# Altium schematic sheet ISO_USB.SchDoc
size A3; SheetNumber: 4; SheetTotal: 4
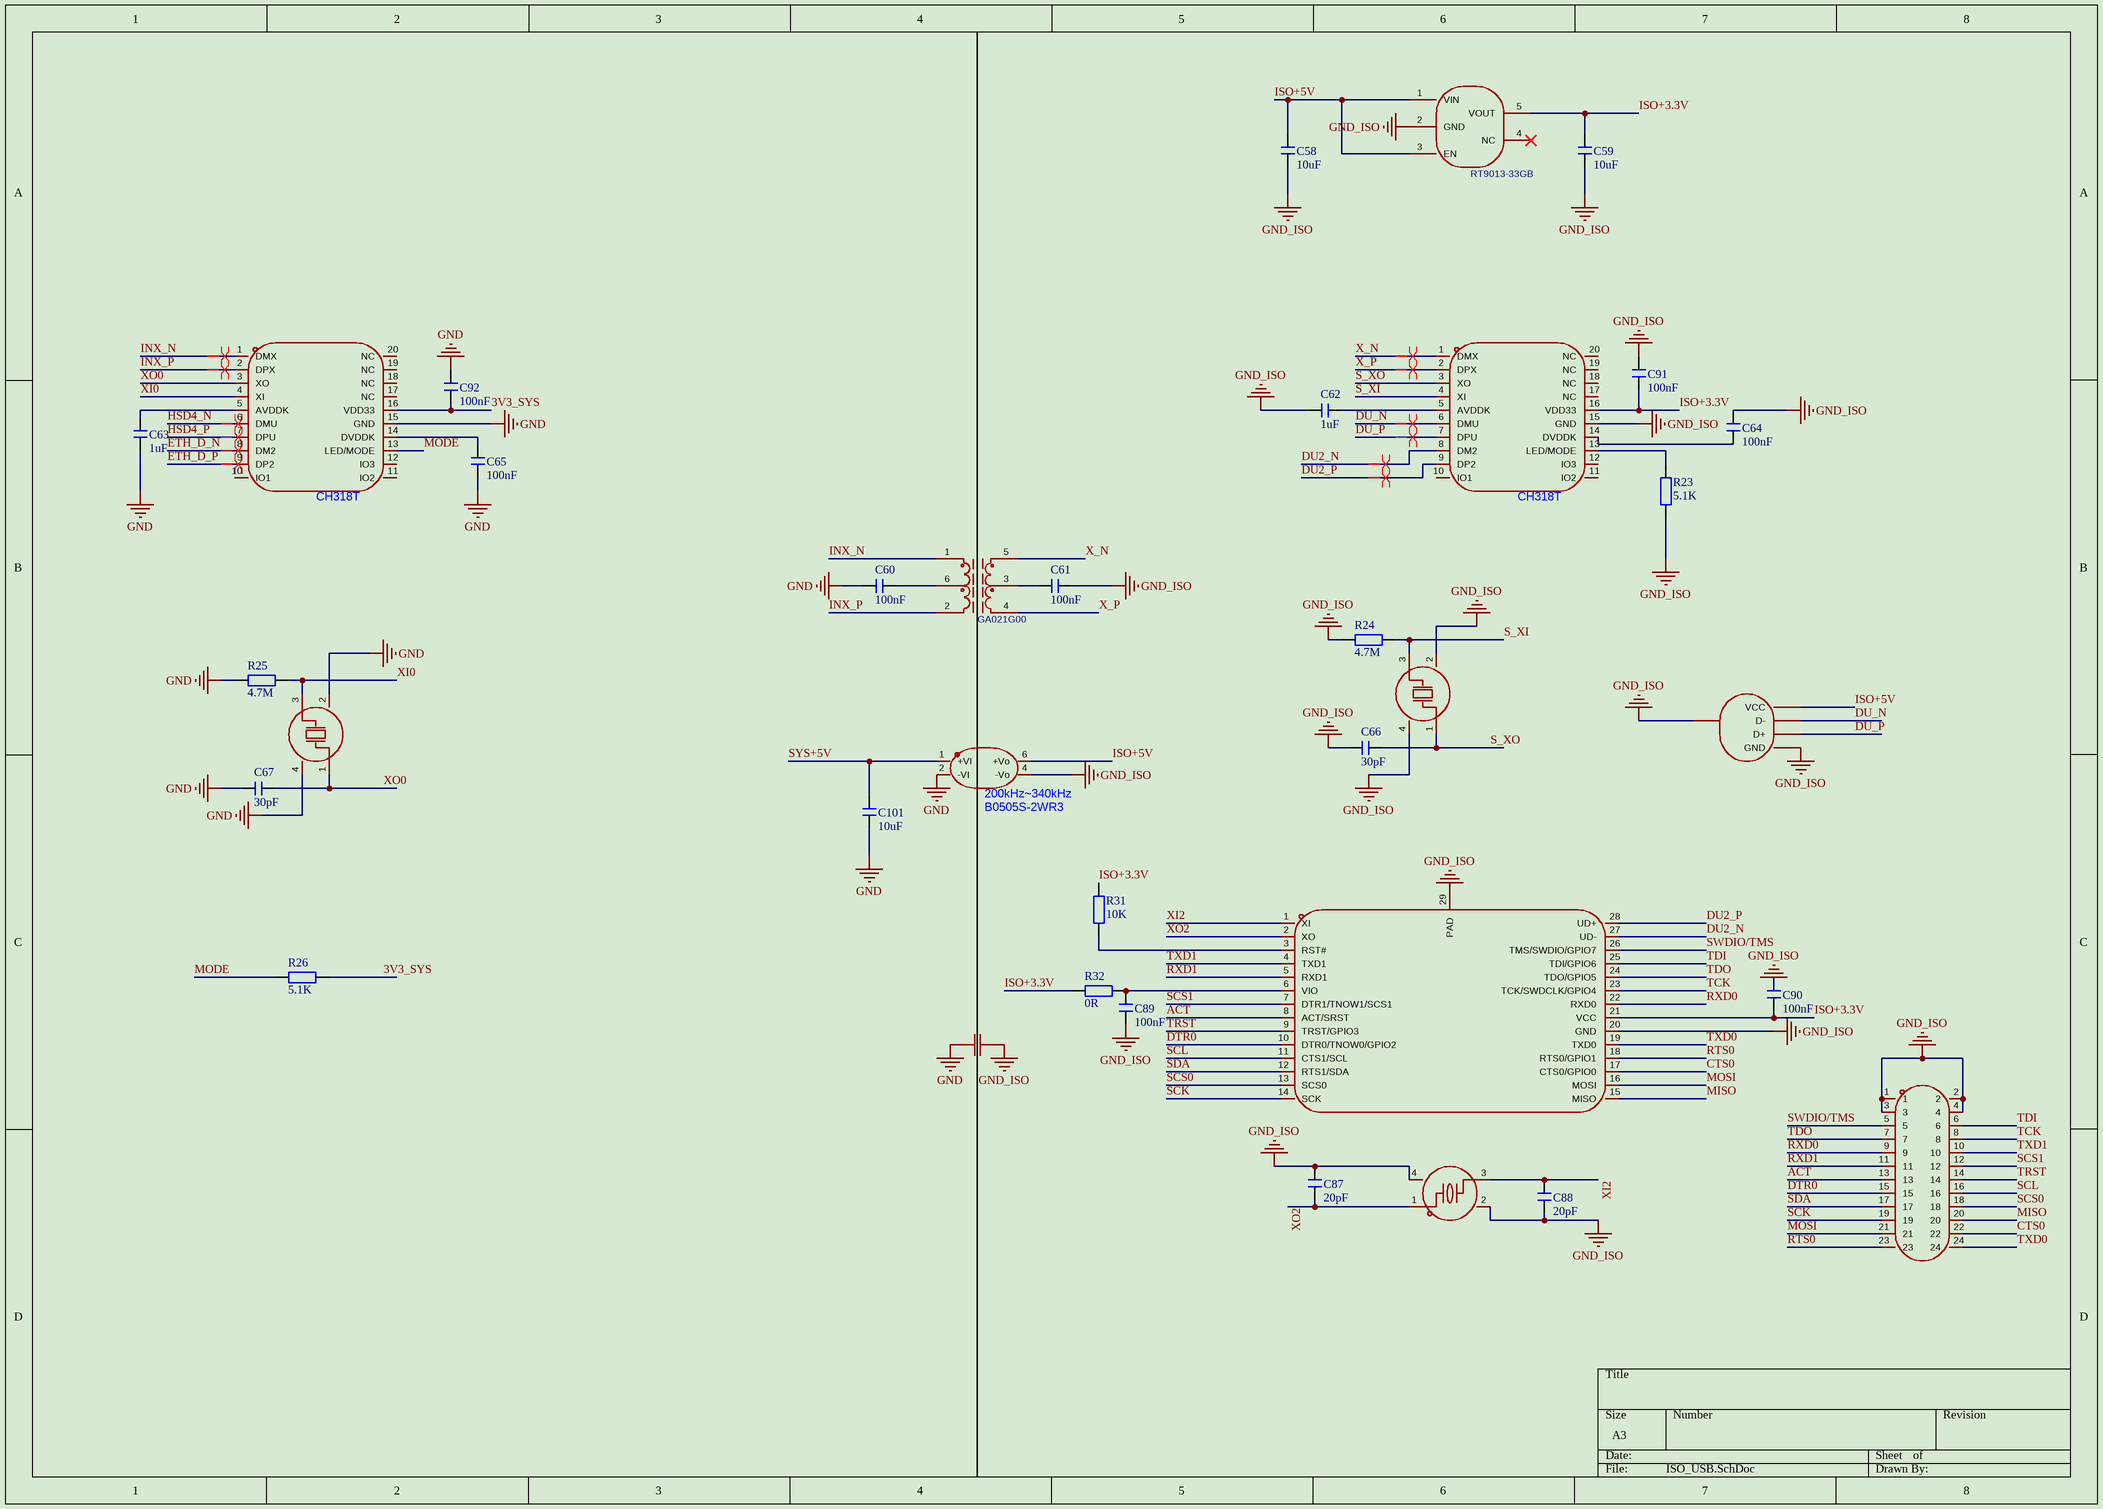
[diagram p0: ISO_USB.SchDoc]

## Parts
C58  10uF  [C 0805_L]
C59  10uF  [C 0805_L]
C60  100nF  [C 0603_L]
C61  100nF  [C 0603_L]
C62  1uF  [C 0603_L]
C63  1uF  [C 0603_L]
C64  100nF  [C 0603_L]
C65  100nF  [C 0603_L]
C66  30pF  [C 0603_L]
C67  30pF  [C 0603_L]
C86  q222m060110fq55250l7579  [CAP-TH_L8.0-W4.5-P7.50-D0.6]  (value not drawn)
C87  20pF  [C 0603_L]
C88  20pF  [C 0603_L]
C89  100nF  [C 0402_L]
C90  100nF  [C 0402_L]
C91  100nF  [C 0603_L]
C92  100nF  [C 0603_L]
C101  10uF  [C 0805_L]
H1  x6521wr-2x12h-c60d30  [HDR-TH_24P-P2.54-H-M-R2-C12-S2.54]  (value not drawn)
R23  5.1K  [R 0603_L]
R24  4.7M  [R 0603_L]
R25  4.7M  [R 0603_L]
R26  5.1K  [R 0603_L]
R31  10K  [R 0402_L]
R32  0R  [R 0402_L]
U8  rt9013-33gb  [SOT-23-5_L3.0-W1.7-P0.95-LS2.8-BL]
U9  ga021g00  [FILTER-SMD_6P-L4.5-W3.4_GA021G00]
U10  LCSC Part Name: CH318T  [TSSOP-20_L6.5-W4.4-P0.65-LS6.4-BL]  (hidden comment: ch318t_c42387966)
U11  LCSC Part Name: CH318T  [TSSOP-20_L6.5-W4.4-P0.65-LS6.4-BL]  (hidden comment: ch318t_c42387966)
U12  value 200kHz~340kHz  ManufacturerPart: B0505S-2WR3  [PWRM-TH_BXXXXS-2WR3]  (hidden comment: b0505s-2wr3_c7465195)
U15  ch347f  [QFN-28_L4.0-W4.0-P0.40-BL-EP2.7]  (value not drawn)
USB5  af 90° wjdg  [USB-A-TH_AF-WJDG]  (value not drawn)
X3  x322520msb4si  [CRYSTAL-SMD_4P-L3.2-W2.5-BL-2]  (value not drawn)
X4  x322520msb4si  [CRYSTAL-SMD_4P-L3.2-W2.5-BL-2]  (value not drawn)
X5  xl2el89coi-111ylc-8m  [CRYSTAL-SMD_4P-L3.2-W2.5-BL-1]  (value not drawn)

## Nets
GND: C60.2 C63.1 C65.1 C67.2 C86.1 C92.1 C101.1 R25.2 U10.15(GND) U12.2(-VI) X4.2(GND) X4.4(GND)
GND_ISO: C58.1 C59.1 C61.1 C62.2 C64.1 C66.2 C86.2 C87.1 C88.2 C89.2 C90.1 C91.1 H1.1 H1.2 H1.3 H1.4 R23.2 R24.2 U8.2(GND) U11.15(GND) U12.4(-Vo) U15.20(GND) U15.29(PAD) USB5.4(GND) USB5.5(SHLD) X3.2(GND) X3.4(GND) X5.2(GND) X5.4(GND)
3V3_SYS: C92.2 R26.1 U10.16(VDD33)
ACT: H1.13 U15.8(ACT/SRST)
CTS0: H1.22 U15.17(CTS0/GPIO0)
DTR0: H1.15 U15.10(DTR0/TNOW0/GPIO2)
DU2_N: U11.8(DM2) U15.27(UD-)
DU2_P: U11.9(DP2) U15.28(UD+)
DU_N: U11.6(DMU) USB5.2(D-)
DU_P: U11.7(DPU) USB5.3(D+)
ETH_D_N: U10.8(DM2)
ETH_D_P: U10.9(DP2)
HSD4_N: U10.6(DMU)
HSD4_P: U10.7(DPU)
INX_N: U9.1 U10.1(DMX)
INX_P: U9.2 U10.2(DPX)
ISO+3.3V: C59.2 C90.2 C91.2 R31.1 R32.1 U8.5(VOUT) U11.16(VDD33) U15.21(VCC)
ISO+5V: C58.2 U8.1(VIN) U8.3(EN) U12.6(+Vo) USB5.1(VCC)
MISO: H1.20 U15.15(MISO)
MODE: R26.2 U10.13(LED/MODE)
MOSI: H1.21 U15.16(MOSI)
RTS0: H1.23 U15.18(RTS0/GPIO1)
RXD0: H1.9 U15.22(RXD0)
RXD1: H1.11 U15.5(RXD1)
S_XI: R24.1 U11.4(XI) X3.3(OSC2)
S_XO: C66.1 U11.3(XO) X3.1(OSC1)
SCK: H1.19 U15.14(SCK)
SCL: H1.16 U15.11(CTS1/SCL)
SCS0: H1.18 U15.13(SCS0)
SCS1: H1.12 U15.7(DTR1/TNOW1/SCS1)
SDA: H1.17 U15.12(RTS1/SDA)
SWDIO/TMS: H1.5 U15.26(TMS/SWDIO/GPIO7)
SYS+5V: C101.2 U12.1(+VI)
TCK: H1.8 U15.23(TCK/SWDCLK/GPIO4)
TDI: H1.6 U15.25(TDI/GPIO6)
TDO: H1.7 U15.24(TDO/GPIO5)
TRST: H1.14 U15.9(TRST/GPIO3)
TXD0: H1.24 U15.19(TXD0)
TXD1: H1.10 U15.4(TXD1)
X_N: U9.5 U11.1(DMX)
X_P: U9.4 U11.2(DPX)
XI0: R25.1 U10.4(XI) X4.3(OSC2)
XI2: C88.1 U15.1(XI) X5.3
XO0: C67.1 U10.3(XO) X4.1(OSC1)
XO2: C87.2 U15.2(XO) X5.1
NetC60_1: C60.1 U9.6
NetC61_2: C61.2 U9.3
NetC62_1: C62.1 U11.5(AVDDK)
NetC63_2: C63.2 U10.5(AVDDK)
NetC64_2: C64.2 U11.14(DVDDK)
NetC65_2: C65.2 U10.14(DVDDK)
NetC89_1: C89.1 R32.2 U15.6(VIO)
NetR23_1: R23.1 U11.13(LED/MODE)
NetR31_2: R31.2 U15.3(RST#)

Not connected (* = marked no-connect by the designer): U8 4(NC)*; U10 10(IO1) 11(IO2) 12(IO3) 17(NC) 18(NC) 19(NC) 20(NC); U11 10(IO1) 11(IO2) 12(IO3) 17(NC) 18(NC) 19(NC) 20(NC)

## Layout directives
differential pair; differential pair class 90ohm: DU2_N, DU2_P, DU_N, DU_P, ETH_D_N, ETH_D_P, HSD4_N, HSD4_P
differential pair; differential pair class 100ohm: INX_N, INX_P, X_N, X_P

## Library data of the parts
C58-C67 C87-C92 C101 = C: 无极性贴片电容; 版权归属: 源创客; 材质: X7R
C86 = q222m060110fq55250l7579: 容值:2.2nF;精度:±20%;工作电压(AC):300V;防护等级:Y2;; Manufacturer: QNR(勤宏科技); AddInBom: yes; ModelId: 6309ea5c534b4b05939c21f9c59ffb79; ModelTransform: 354.33,177.165,0,0,0,0,0,0,-196.85; Value: 2.2nF; Tolerance: ±20%; Voltage(AC): 300V; Ratings: Y2
H1 = x6521wr-2x12h-c60d30: 插针结构:2x12P;间距:2.54mm;行距:2.54mm;圆针/方针:方针;排数:双排;总PIN位数:24P;额定电流:3A;额定电压:250V;配合针长度:-;塑高:2.5mm;端接针长度:-;触头材质:黄铜;触头镀层:金;工作温度:-40℃~+105℃;颜色:黑色;; Manufacturer: XKB Connection(中国星坤); Symbol: X6521WR-2×12H-C30D60; AddInBom: yes; ModelId: c87603f207fc4d939d696e0588895b6d; ModelName: HDR-TH_24P-P2.54-M-WI-2X12P; ModelTransform: 1199.9976,507.873,0,0,0,0,0,-190.945,-118.11; Pin Structure: 2x12P; Pitch: 2.54mm; Circluar Pins/Square Pins: 方针; Current Rating: 3A; Voltage Rating (Max): 250V
R23-R26 R31 R32 = R: 贴片电阻; 版权归属: 源创客
U8 = rt9013-33gb: 输出极性:正极;工作电压:5.5V;输出电压:3.3V;输出电流:500mA;电源纹波抑制比(PSRR):50dB@(10kHz);输出类型:固定;; Manufacturer: RICHTEK(立锜); AddInBom: yes; ModelId: 0a2a1b8f50944f73965918ad6e5fe167; ModelName: SOT-23-5_L2.9-W1.6-H1.1-LS2.8-P0.95; ModelTransform: 118.60433,114.173,0,90,0,0,0.0005,0.0005,0; Output Configuration: 正极; Voltage - Supply: 5.5V; Output Voltage: 3.3V; Output Current: 500mA; Voltage Dropout: 400mV@(500mA); standby current: 25uA; Noise: 30uVrms; Output Type: 固定; Number of Outputs: 1
U9 = ga021g00: 线路数:4;电感@频率:120uH@100kHz;阻抗@频率:-;直流电阻(DCR):1.2Ω;; Manufacturer: CND-tek(磁联达); AddInBom: yes; ModelId: 47185f9e5e204908b0c4690c3dbe201c; ModelTransform: 181.18074,133.858,0,0,0,0,0.001,-0.001,0; Number of Lines: 4; Current Rating: 720mA; Voltage Withstand: 1.5kV; DC Resistance(DCR): 1.2Ω
U10 U11 = ch318t_c42387966: 是高速USB信号隔离和传输距离延长控制芯片，支持电容耦合或者网络变压器耦合，不但实现了对USB信号的隔离，同时实现了对USB信号的实时中转和传输距离延长。此外，芯片自身带有USBHUB功能，上行端口支持USB2.0高速，下行端口支持USB2.0高速480Mbps、全速12Mbps和低速1.5Mbps。可以用于高速USB信号隔离、隔离HUB、延长HUB等。; Manufacturer: WCH(南京沁恒); AddInBom: yes; ModelId: c491f68934b34c649df5890a1d97cd0f; ModelName: TSSOP-20_L6.5-W4.4-H1.0-LS6.4-P0.65; ModelTransform: 251.969,255.906,0,90,0,0,0.0005,0,0; Protocol: USB 1.1；USB 2.0; Data Rate(Max): 480Mbit/s; Voltage - Supply: 3.3V
U12 = b0505s-2wr3_c7465195: DC-DC隔离电源模块:输入5V(4.5V~5.5V)@@输出5V 400mA 2W@@输出短路保护@@输入输出隔离耐压1.5KV@@SIP7; Manufacturer: EVISUN(易成); AddInBom: yes; ModelId: 14934276571d427a996fe673d734980f; ModelTransform: 773.6205,277.5585,0,0,0,0,49.409,-102.953,-157.48; Number of Outputs: 1; Output Power: 2W; Conversion Efficiency: 88%; Output Voltage: 5V; Capacitive Load(Max): 2400uF; Isolation Voltage(Vrms): 1.5kV; Quiescent Supply Current: 8mA; Ripple Noise: 75mVp-p; Voltage Regulation: 非稳压型
U15 = ch347f: 应用功能:USB转UART；USB转SPI；USB转SWD；USB转I2C；USB转JTAG;USB协议版本:USB 2.0;通道数:2;数据速率:480Mbps;; Manufacturer: WCH(南京沁恒); AddInBom: yes; ModelId: 026209c2d38043429298993ef2ab37e8; ModelTransform: 158.267,158.267,0,0,0,0,0,0,0; USB Protocol: USB 2.0; Number of Channels: 2; Voltage - Supply: 3V~3.6V; Current - Supply: 38mA; Quiescent Supply Current: 260uA
USB5 = af 90° wjdg: 连接器类型:Type-A;协议标准:USB 2.0;公母:母;安装方式:弯插;触点数量:4P;端口数量:1;额定电流 - 电源:1.5A;工作温度:-25℃~+85℃;; Manufacturer: SHOU HAN(首韩); AddInBom: yes; ModelId: 268f7f19b8674295a50f5e7a4a3dee80; ModelName: USB-A-TH_4P-L14.5-W14.0-H7.6-S2.71; ModelTransform: 610.19406,551.18,0,0,0,0,0,-192.915,-149.606; Connector Type: Type-A; Protocol Standard: USB 2.0; Gender: 母; Number of Contacts: 4P; Number of Ports: 1; Current Rating-Power: 1.5A; Voltage Rating: 30V; Connect-Disconnect Life: 5千次; Detection color: 白色
X3 X4 = x322520msb4si: 晶振类型:贴片晶振;频率:20MHz;常温频差:±10ppm;负载电容:20pF;频率稳定度:±20ppm;; Manufacturer: YXC(扬兴晶振); AddInBom: yes; ModelId: 6000dc8adf4c4082a91df701f77194e1; ModelTransform: 125.984,98.425,0,0,0,0,-0.001,0.003,0; Value: 20MHz; Normal temperature Frequency Tolerance: ±10ppm; Load Capacitance: 20pF; Frequency Stability: ±20ppm; Equivalent Series Resistance(ESR): 50Ω
X5 = xl2el89coi-111ylc-8m: 晶振类型:贴片晶振;频率:8MHz;常温频差:±10ppm;负载电容:12pF;频率稳定度:±20ppm;; Manufacturer: YXC(扬兴晶振); AddInBom: yes; ModelId: 4495b492a02c4f389e505ec8ae3aaf1b; ModelTransform: 125.984,98.425,0,0,0,0,0,0,0; Value: 8MHz; Normal temperature Frequency Tolerance: ±10ppm; Load Capacitance: 12pF; Frequency Stability: ±20ppm; Equivalent Series Resistance(ESR): 180Ω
